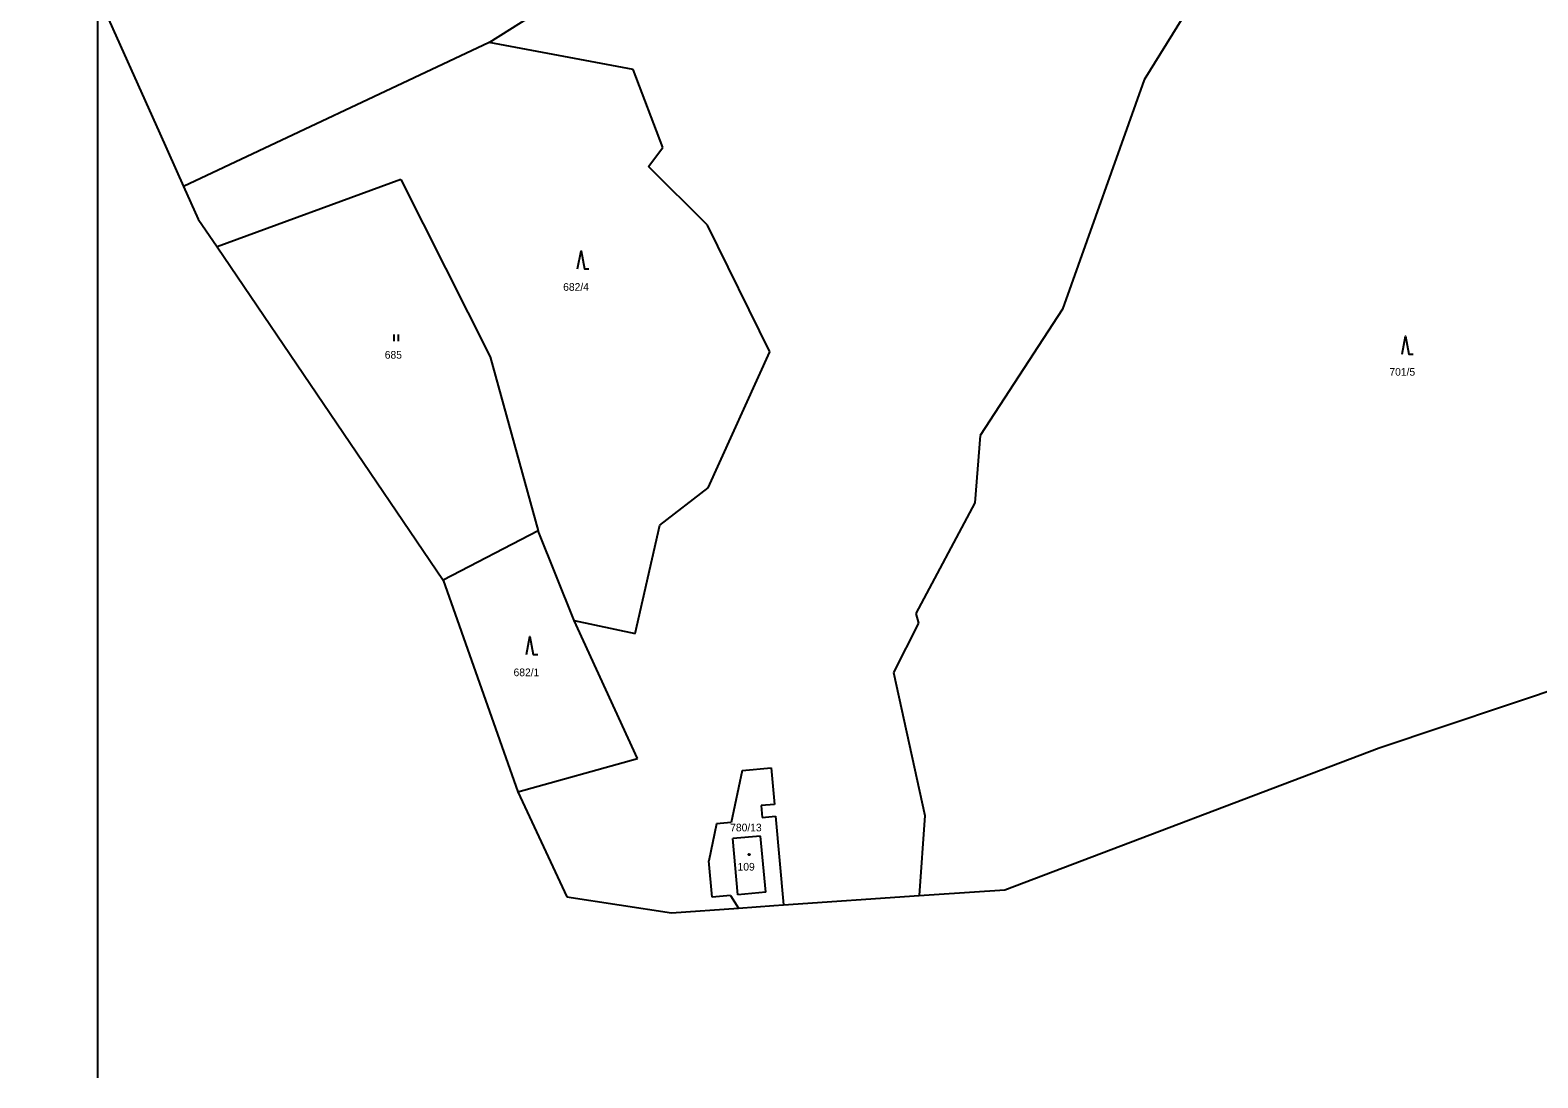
# Model space of a CAD drawing. Extents: x -801907 to -800293, y -1017000 to -1015684.
# Drawn here: x -801264.9 to -800931.6, y -1017000 to -1016768.4 of the extents above; entities that cross this region are included whole.
import ezdxf

# ---------------------------------------------------------------- set-up
doc = ezdxf.new("R2010")
doc.units = 0
for name, color, linetype in [('Default', 7, 'Continuous'), ('KLADY_ZMVM', 7, 'Continuous'), ('KN_HRANICE', 7, 'Continuous'), ('KN_KULTURY', 7, 'Continuous'), ('KN_PARCELY', 7, 'Continuous')]:
    doc.layers.add(name, color=color, linetype=linetype)

# ---------------------------------------------------------------- blocks, each defined once
blk = doc.blocks.new('306')
at = {"layer": 'Default'}
for p, q in [((-0.5, 1.5), (-0.5, 0)), ((0.5, 0), (0.5, 1.5))]:
    blk.add_line(p, q, dxfattribs=at)
blk = doc.blocks.new('308')
at = {"layer": 'Default'}
blk.add_lwpolyline([(-0.75, 0), (0, 4), (0.75, 0), (1.75, 0)], dxfattribs=at)
blk = doc.blocks.new('402')
at = {"layer": 'Default'}
blk.add_lwpolyline([(0.09, 0.15), (0.18, 0), (0.09, -0.15), (-0.09, -0.15), (-0.18, 0), (-0.09, 0.15), (0.09, 0.15)], dxfattribs=at)

msp = doc.modelspace()

# ---------------------------------------------------------------- linework, layer by layer
at = {"layer": 'KLADY_ZMVM'}
msp.add_lwpolyline([(-801250, -1016000), (-801250, -1016500), (-801250, -1017000)], dxfattribs=at)
at = {"layer": 'KN_HRANICE'}
for p, q in [((-801264.86, -1016727.26), (-801236.19, -1016791.22)), ((-801163.4, -1016771.13), (-801141.65, -1016757.37)), ((-801010.08, -1016765.6), (-801018.62, -1016779.34)), ((-801163.4, -1016771.13), (-801230.93, -1016802.94)), ((-801131.53, -1016777.03), (-801163.4, -1016771.13)), ((-801124.98, -1016794.3), (-801131.53, -1016777.03)), ((-801018.62, -1016779.34), (-801036.69, -1016830.07)), ((-801236.19, -1016791.22), (-801230.93, -1016802.94)), ((-801128.15, -1016798.48), (-801124.98, -1016794.3)), ((-801115.13, -1016811.47), (-801128.15, -1016798.48)), ((-801182.9, -1016801.41), (-801223.54, -1016816.29)), ((-801182.9, -1016801.41), (-801163.18, -1016840.62)), ((-801230.93, -1016802.94), (-801227.69, -1016810.17)), ((-801227.69, -1016810.17), (-801223.54, -1016816.29)), ((-801101.38, -1016839.47), (-801115.13, -1016811.47)), ((-801223.54, -1016816.29), (-801173.56, -1016890)), ((-801036.69, -1016830.07), (-801054.84, -1016857.97)), ((-801163.18, -1016840.62), (-801152.53, -1016879.07)), ((-801114.98, -1016869.57), (-801101.38, -1016839.47)), ((-801054.84, -1016857.97), (-801056.01, -1016872.88)), ((-801125.7, -1016877.8), (-801114.98, -1016869.57)), ((-801056.01, -1016872.88), (-801069.07, -1016897.37)), ((-801152.53, -1016879.07), (-801173.56, -1016890)), ((-801144.58, -1016898.92), (-801152.53, -1016879.07)), ((-801131.1, -1016901.79), (-801125.7, -1016877.8)), ((-801173.56, -1016890), (-801157.02, -1016936.79)), ((-801130.62, -1016929.41), (-801144.58, -1016898.92)), ((-801144.58, -1016898.92), (-801131.1, -1016901.79)), ((-801069.07, -1016897.37), (-801068.48, -1016899.49)), ((-801068.48, -1016899.49), (-801073.99, -1016910.36)), ((-801073.99, -1016910.36), (-801067.12, -1016942.01)), ((-800966.67, -1016927.02), (-800919.72, -1016911.28)), ((-801049.4, -1016958.4), (-800966.67, -1016927.02)), ((-801157.02, -1016936.79), (-801130.62, -1016929.41)), ((-801107.46, -1016932.05), (-801109.88, -1016943.55)), ((-801107.46, -1016932.05), (-801101.09, -1016931.47)), ((-801101.09, -1016931.47), (-801100.35, -1016939.54)), ((-801157.02, -1016936.79), (-801146.24, -1016959.95)), ((-801100.35, -1016939.54), (-801103.29, -1016939.8)), ((-801103.29, -1016939.8), (-801103.05, -1016942.44)), ((-801103.05, -1016942.44), (-801100.11, -1016942.18)), ((-801100.11, -1016942.18), (-801098.33, -1016961.78)), ((-801067.12, -1016942.01), (-801068.35, -1016959.71)), ((-801113.17, -1016943.85), (-801114.84, -1016951.99)), ((-801109.88, -1016943.55), (-801113.17, -1016943.85)), ((-801103.39, -1016946.53), (-801109.56, -1016947.09)), ((-801108.43, -1016959.54), (-801109.56, -1016947.09)), ((-801102.26, -1016958.98), (-801103.39, -1016946.53)), ((-801114.11, -1016960.06), (-801114.84, -1016951.99)), ((-801102.26, -1016958.98), (-801108.43, -1016959.54)), ((-801065.05, -1016959.48), (-801049.4, -1016958.4)), ((-801146.24, -1016959.95), (-801123.1, -1016963.5)), ((-801123.1, -1016963.5), (-801108.28, -1016962.47)), ((-801110.03, -1016959.68), (-801114.11, -1016960.06)), ((-801110.03, -1016959.68), (-801108.28, -1016962.47)), ((-801108.28, -1016962.47), (-801100.45, -1016961.93)), ((-801100.45, -1016961.93), (-801098.33, -1016961.78)), ((-801098.33, -1016961.78), (-801068.35, -1016959.71)), ((-801068.35, -1016959.71), (-801065.05, -1016959.48))]:
    msp.add_line(p, q, dxfattribs=at)

# ---------------------------------------------------------------- block references
at = {"layer": 'KN_KULTURY'}
for name, p in [('308', (-801143.08, -1016821.17)), ('306', (-801183.93, -1016837.13)), ('308', (-800960.85, -1016840.02)), ('308', (-801154.39, -1016906.41)), ('402', (-801105.93, -1016950.65))]:
    msp.add_blockref(name, p, dxfattribs=at)

# ---------------------------------------------------------------- texts
at = {"layer": 'KN_PARCELY'}
for s, p in [('682/4', (-801147.03, -1016825.99)), ('685', (-801186.47, -1016841)), ('701/5', (-800964.39, -1016844.76)), ('682/1', (-801158, -1016911.2)), ('780/13', (-801110.11, -1016945.51)), ('109', (-801108.48, -1016954.18))]:
    msp.add_text(s, height=1.7, dxfattribs=at).set_placement(p)

doc.saveas('drawing.dxf')
